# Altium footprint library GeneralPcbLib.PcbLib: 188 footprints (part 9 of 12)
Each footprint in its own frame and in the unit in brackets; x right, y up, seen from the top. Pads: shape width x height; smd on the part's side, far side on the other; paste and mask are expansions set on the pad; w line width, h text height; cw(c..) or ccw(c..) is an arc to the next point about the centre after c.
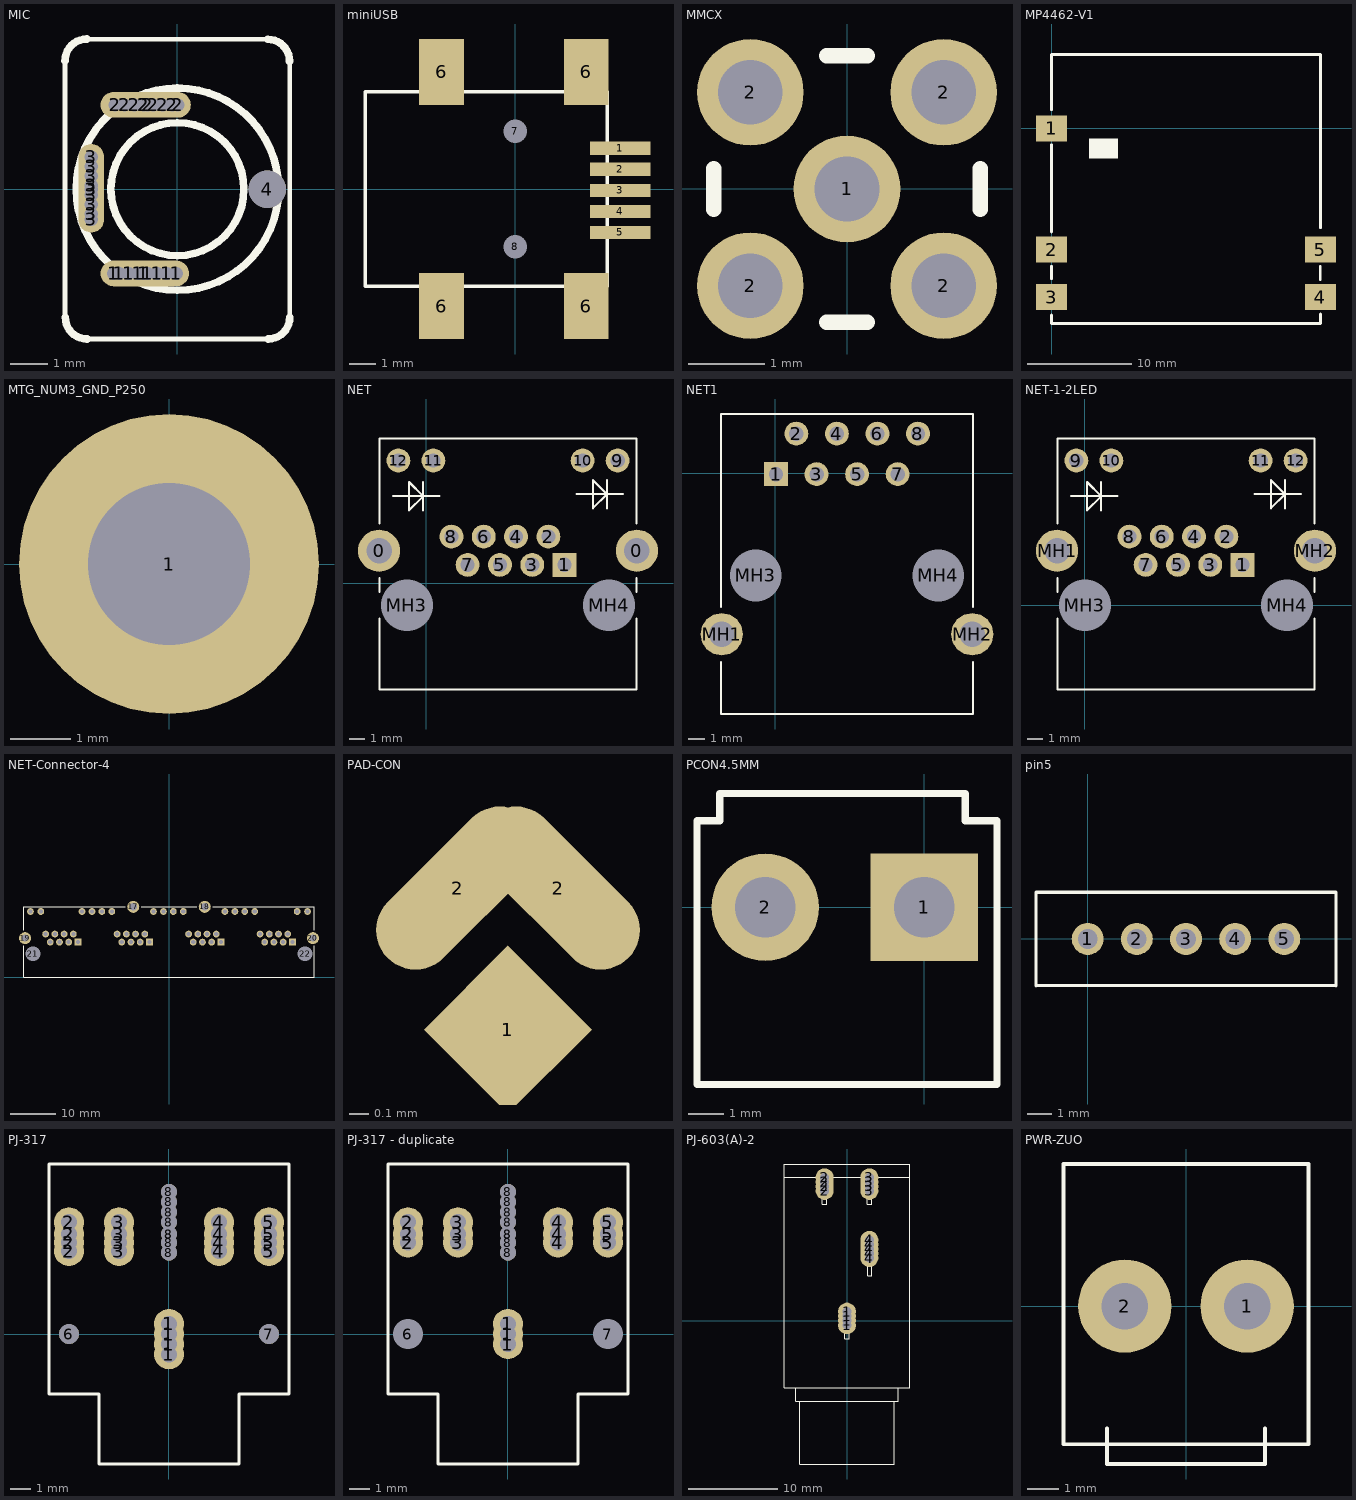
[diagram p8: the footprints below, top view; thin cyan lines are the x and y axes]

## MIC [mm] "TC38-47"
pads (30):
  round 0.685 hole 0.35: 1(-1.7,-2.25) 1(-1.554,-2.25) 1(-1.3,-2.25) 1(-1.046,-2.25) 1(-0.792,-2.25) 1(-0.538,-2.25) 1(-0.284,-2.25) 1(-0.03,-2.25) 2(-1.662,2.25) 2(-1.408,2.25) 2(-1.154,2.25) 2(-0.9,2.25) 2(-0.646,2.25) 2(-0.392,2.25) 2(-0.138,2.25) 2(0.008,2.25) 3(-2.3,-0.808) 3(-2.3,-0.662) 3(-2.3,-0.408) 3(-2.3,-0.154) 3(-2.3,0.1) 3(-2.3,0.354) 3(-2.3,0.608) 3(-2.3,0.862)
  oval 2.3x0.685 hole 0.35: 1(-0.9,-2.25) 2(-0.9,2.25) 2(-0.792,2.25)
  oval 0.685x2.3 hole 0.35: 3(-2.3,-0.008) 3(-2.3,0)
  round 1 hole 1: 4(2.4,0)
Top Overlay:
  circle w0.203: c0,0 r1.775
  circle w0.203: c0,0 r2.7
  lines w0.127: -3,-3.42 -3,3.429 ; -2.54,4 2.413,4 ; -2.413,-4 2.42,-4 ; 3,-3.429 3,3.42
  lines w0.203: -3,3.429 cw(c-2.42,3.429) -2.42,4.009 ; -2.993,-3.42 ccw(c-2.413,-3.42) -2.413,-4 ; 2.413,4 cw(c2.413,3.42) 2.993,3.42 ; 2.42,-4 ccw(c2.42,-3.42) 3,-3.42

## miniUSB [mm] "5芯miniUSB座"
height 4
pads (11):
  rect 2.3x0.5 smd: 1(3.999,1.549) 2(3.999,0.749) 3(3.999,-0.051) 4(3.999,-0.851) 5(3.999,-1.651)
  rect 1.7x2.5 smd: 6(-2.8,-4.45) 6(-2.8,4.45) 6(2.7,-4.45) 6(2.7,4.45)
  round 0.5 hole 0.9: 7(0,2.2) 8(0,-2.2)
Top Overlay:
  lines w0.127: -5.7,-3.7 -5.7,3.7 3.5,3.7 3.5,-3.7 -5.7,-3.7

## MMCX [mm]
pads (5):
  round 1.4 hole 0.85: 1(0,0) 2(-1.27,-1.27) 2(-1.27,1.27) 2(1.27,-1.27) 2(1.27,1.27)
Top Overlay:
  lines w0.2: -1.75,-0.27 -1.75,0.27 ; -0.27,-1.75 0.27,-1.75 ; -0.27,1.75 0.27,1.75 ; 1.75,-0.27 1.75,0.27

## MP4462-V1 [mm]
pads (5):
  rect 3x2.5 smd: 1(0,0) 2(0,-11.684) 3(0,-16.256) 4(25.908,-16.256) 5(25.908,-11.684)
Top Overlay:
  rectangle: 3.6,-2.888 6.4,-0.988
  lines w0.254: 0,-17.988 0,-18.796 25.908,-18.796 25.908,-17.888 ; 0,-14.488 0,-13.288 ; 0,-9.988 0,-1.588 ; 0,1.812 0,7.112 25.908,7.112 25.908,-9.588 ; 25.9,-14.588 25.9,-13.288

## MTG_NUM3_GND_P250 [mm]
pads (1):
  round 5 hole 2.7: 1(0,0)

## NET [mm] "B563S-8850-U006"
pads (16):
  round 2.65 hole 1.6: 0(-2.953,2.029) 0(13.253,2.029)
  rect 1.5x1.5 hole 0.9: 1(8.706,1.14)
  round 1.5 hole 0.9: 2(7.69,2.918) 3(6.674,1.14) 4(5.658,2.918) 5(4.642,1.14) 6(3.626,2.918) 7(2.61,1.14) 8(1.594,2.918) 9(12.04,7.7) 10(9.84,7.7) 11(0.46,7.7) 12(-1.74,7.7)
  round 2.95 hole 3.25 unplated: MH3(-1.2,-1.4) MH4(11.5,-1.4)
Top Overlay:
  lines w0.127: -2.94,-2.246 -2.94,-6.68 13.24,-6.68 13.24,-2.246 ; -2.94,-0.554 -2.94,0.306 ; -2.94,3.752 -2.94,9.07 13.24,9.07 13.24,3.752 ; -2.089,5.458 0.832,5.458 ; -0.184,4.569 -0.184,6.347 ; 9.468,5.585 12.389,5.585 ; 11.373,4.696 11.373,6.474 ; 13.24,-0.554 13.24,0.306 ; -1.073,4.569 -1.073,6.347 -0.184,5.458 -1.073,4.569 ; 10.484,4.696 11.373,5.585 10.484,6.474 10.484,4.696

## NET1 [mm] "立式无LED"
height 10
pads (12):
  rect 1.5x1.5 hole 0.9: 1(0.055,-0.07)
  round 1.5 hole 0.9: 2(1.325,2.47) 3(2.595,-0.07) 4(3.865,2.47) 5(5.135,-0.07) 6(6.405,2.47) 7(7.675,-0.07) 8(8.945,2.47)
  round 2.65 hole 1.6: MH1(-3.349,-10.103) MH2(12.349,-10.103)
  round 2.95 hole 3.25 unplated: MH3(-1.215,-6.42) MH4(10.215,-6.42)
Top Overlay:
  lines w0.127: -3.4,-11.827 -3.4,-15.1 12.4,-15.1 12.4,-11.827 ; -3.4,-8.379 -3.4,3.7 12.4,3.7 12.4,-8.379

## NET-1-2LED [mm]
pads (16):
  rect 1.5x1.5 hole 0.9: 1(9.906,2.54)
  round 1.5 hole 0.9: 2(8.89,4.318) 3(7.874,2.54) 4(6.858,4.318) 5(5.842,2.54) 6(4.826,4.318) 7(3.81,2.54) 8(2.794,4.318) 9(-0.54,9.1) 10(1.66,9.1) 11(11.04,9.1) 12(13.24,9.1)
  round 2.65 hole 1.6: MH1(-1.753,3.429) MH2(14.453,3.429)
  round 2.95 hole 3.25 unplated: MH3(0,0) MH4(12.7,0)
Top Overlay:
  lines w0.127: -1.74,-0.846 -1.74,-5.28 14.44,-5.28 14.44,-0.846 ; -1.74,0.846 -1.74,1.706 ; -1.74,5.152 -1.74,10.47 14.44,10.47 14.44,5.152 ; -0.889,6.858 2.032,6.858 ; 1.016,5.969 1.016,7.747 ; 10.668,6.985 13.589,6.985 ; 12.573,6.096 12.573,7.874 ; 14.44,0.846 14.44,1.706 ; 0.127,5.969 0.127,7.747 1.016,6.858 0.127,5.969 ; 11.684,6.096 12.573,6.985 11.684,7.874 11.684,6.096

## NET-Connector-4 [mm]
pads (54):
  round 1.5 hole 0.9: 1(-30.531,14.47) 2(-28.245,14.47) 3(-19.177,14.47) 4(-16.975,14.47) 5(-14.802,14.47) 6(-12.6,14.47) 7(-3.429,14.47) 8(-1.227,14.47) 9(0.946,14.47) 10(3.148,14.47) 11(12.319,14.47) 12(14.521,14.47) 13(16.694,14.47) 14(18.896,14.47) 15(28.245,14.47) 16(30.531,14.47) A2(-21.082,9.498) A3(-22.098,7.72) A4(-23.114,9.498) A5(-24.13,7.72) A6(-25.146,9.498) A7(-26.162,7.72) A8(-27.178,9.498) B2(-5.334,9.498) B3(-6.35,7.72) B4(-7.366,9.498) B5(-8.382,7.72) B6(-9.398,9.498) B7(-10.414,7.72) B8(-11.43,9.498) C2(10.414,9.498) C3(9.398,7.72) C4(8.382,9.498) C5(7.366,7.72) C6(6.35,9.498) C7(5.334,7.72) C8(4.318,9.498) D2(26.162,9.498) D3(25.146,7.72) D4(24.13,9.498) D5(23.114,7.72) D6(22.098,9.498) D7(21.082,7.72) D8(20.066,9.498)
  round 2.65 hole 1.6: 17(-7.874,15.492) 18(7.874,15.492) 19(-31.725,8.609) 20(31.725,8.609)
  round 2.95 hole 3.25 unplated: 21(-29.972,5.18) 22(29.972,5.18)
  rect 1.5x1.5 hole 0.9: A1(-20.066,7.72) B1(-4.318,7.72) C1(11.43,7.72) D1(27.178,7.72)
Top Overlay:
  lines w0.127: -31.997,6.906 -31.997,0 31.997,0 31.997,6.906 ; -31.997,10.312 -31.997,15.47 -9.599,15.47 ; -6.149,15.47 6.149,15.47 ; 9.599,15.47 31.997,15.47 31.997,10.312

## PAD-CON [mm] "焊锡连接点"
pads (3):
  rect 0.6x0.6 smd rot 45: 1(-2.54,-3)
  oval 0.4x1 smd rot 135: 2(-2.794,-2.286)
  oval 0.4x1 smd rot 45: 2(-2.286,-2.286)

## PCON4.5MM [mm] "带锁白色2位大功率 VH-2A/2Y"
height 12
pads (2):
  rect 3x3 hole 1.7: 1(0,0)
  round 3 hole 1.7: 2(-4.445,0)
Top Overlay:
  lines w0.203: -6.35,-4.953 2.032,-4.953 2.032,2.413 1.143,2.413 1.143,3.175 -5.715,3.175 -5.715,2.413 -6.35,2.413 -6.35,-4.953

## pin5 [mm] "Connector; Plug"
height 4.3
pads (5):
  round 1.3 hole 0.8: 1(0,0) 2(2,0) 3(4,0) 4(6,0) 5(8,0)
Top Overlay:
  lines w0.127: -2.1,-1.905 -2.1,1.9 10.1,1.9 ; -2.1,-1.9 10.1,-1.9 ; 10.1,-1.905 10.1,1.85

## PJ-317 [mm] "音频座"
height 10
pads (30):
  round 1.5 hole 0.8: 1(0,-1.016) 1(0,-0.508) 1(0,0) 1(0,0.508) 2(-5,4.144) 2(-5,4.572) 2(-5,5) 2(-5,5.588) 3(-2.5,4.144) 3(-2.5,4.572) 3(-2.5,5) 3(-2.5,5.588) 4(2.5,4.144) 4(2.5,4.572) 4(2.5,5) 4(2.5,5.588) 5(5,4.144) 5(5,4.572) 5(5,5) 5(5,5.588)
  round 1 hole 1: 6(-5,0) 7(5,0)
  round 0.8 hole 0.8: 8(0,4.064) 8(0,4.572) 8(0,5) 8(0,5) 8(0,5.588) 8(0,6.096) 8(0,6.604) 8(0,7.112)
Top Overlay:
  lines w0.127: -6,-3 -6,8.5 6,8.5 6,-3 3.5,-3 3.5,-6.5 -3.5,-6.5 -3.5,-3 -6,-3

## PJ-317 - duplicate [mm] "音频座"
height 10
pads (25):
  round 1.5 hole 0.8: 1(0,-0.508) 1(0,0) 1(0,0.508) 2(-5,4.572) 2(-5,5) 2(-5,5.588) 3(-2.5,4.572) 3(-2.5,5) 3(-2.5,5.588) 4(2.5,4.572) 4(2.5,5) 4(2.5,5.588) 5(5,4.572) 5(5,5) 5(5,5.588)
  round 1 hole 1.5: 6(-5,0) 7(5,0)
  round 0.8 hole 0.8: 8(0,4.064) 8(0,4.572) 8(0,5) 8(0,5) 8(0,5.588) 8(0,6.096) 8(0,6.604) 8(0,7.112)
Top Overlay:
  lines w0.127: -6,-3 -3.5,-3 -3.5,-6.5 3.5,-6.5 3.5,-3 6,-3 6,8.5 -6,8.5 -6,-3

## PJ-603(A)-2 [mm] "会议话筒音频座"
height 10.4
pads (17):
  round 2 hole 1: 1(0,-0.508) 1(0,0) 1(0,0.508) 1(0,1.016) 2(-2.5,14.492) 2(-2.5,15) 2(-2.5,15.508) 2(-2.5,16.016) 3(2.5,14.492) 3(2.5,15) 3(2.5,15.508) 3(2.5,16.016) 4(2.5,7) 4(2.5,7.508) 4(2.5,8.016) 4(2.5,8.524) 4(2.5,9.032)
Top Overlay:
  lines w0.127: -7,16 7,16 ; -5.75,-7.5 -5.75,-9 5.75,-9 5.75,-7.5 ; -5.25,-9 -5.25,-14.5 -5.25,-16 5.25,-16 5.25,-14.5 5.25,-9 ; 7,-7.5 7,17.5 -7,17.5 -7,-7.5 7,-7.5 ; -2.75,13 -2.75,15 -2.25,15 -2.25,13 -2.75,13 ; -2.75,14 -2.75,16 -2.25,16 -2.25,14 -2.75,14 ; -0.25,-2 0.25,-2 0.25,0 -0.25,0 -0.25,-2 ; 2.25,13 2.25,15 2.75,15 2.75,13 2.25,13 ; 2.25,14 2.25,16 2.75,16 2.75,14 2.25,14 ; 2.29,5 2.29,7 2.79,7 2.79,5 2.29,5

## PWR-ZUO [mm] "白色塑料插座--免帐"
height 6
pads (2):
  round 3 hole 1.5: 1(1.969,0) 2(-1.969,0)
Top Overlay:
  lines w0.127: -2.54,-3.937 -2.54,-5.08 2.54,-5.08 2.54,-3.937 ; -3.937,-4.445 3.937,-4.445 3.937,0.889 3.937,4.572 -3.937,4.572 -3.937,0.889 -3.937,-4.445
